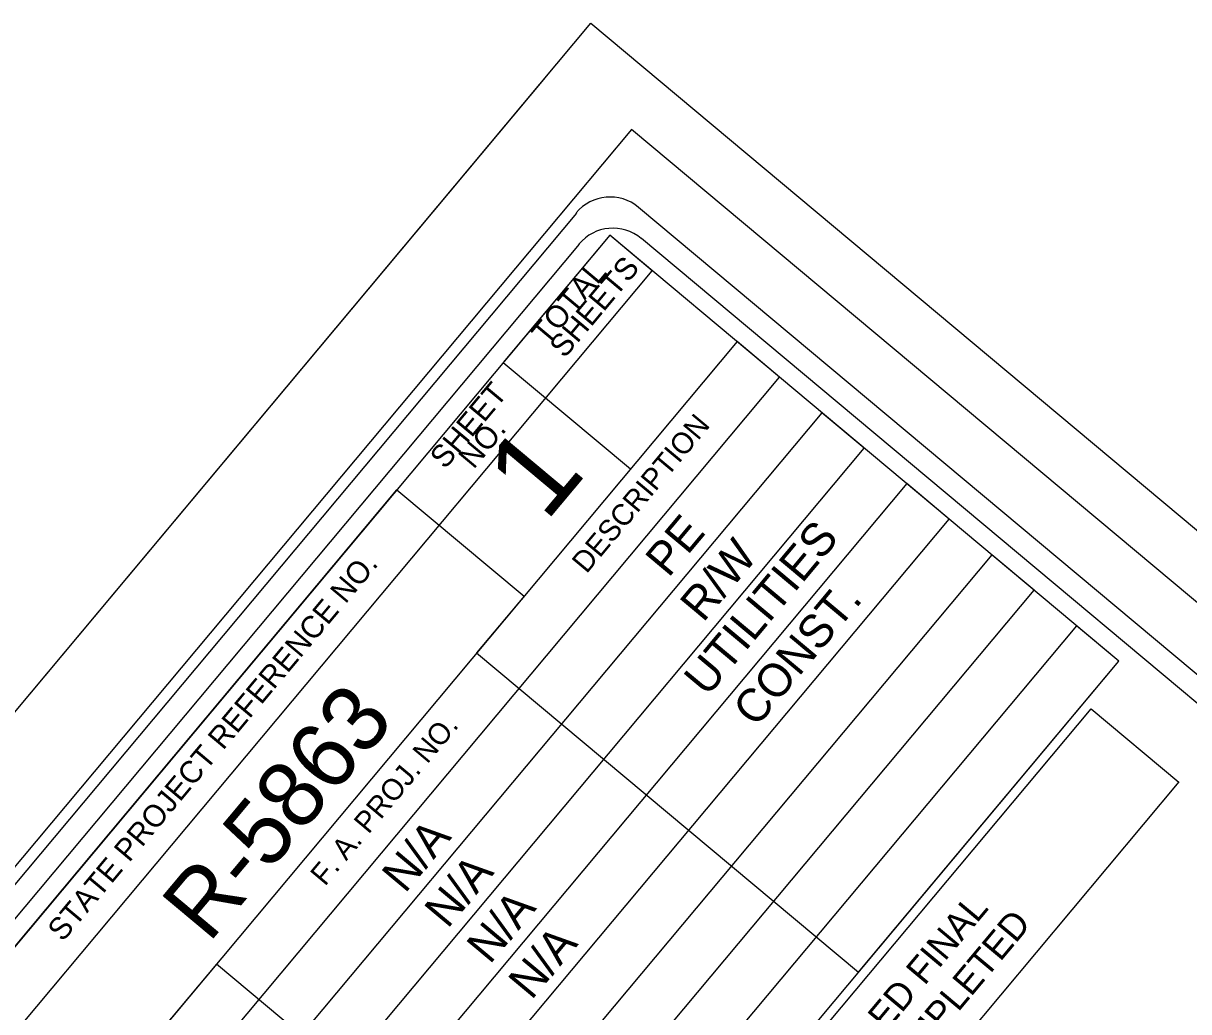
# Model space of a CAD drawing. Extents: x 555292 to 2368606, y 503623 to 1171444.
# Drawn here: x 2359845 to 2361161, y 1167910 to 1169027 of the extents above; entities that cross this region are included whole.
import ezdxf

# ---------------------------------------------------------------- set-up
doc = ezdxf.new("R2010")
doc.units = 0
for name, color, linetype in [('Default', 7, 'Continuous'), ('Sheet Cutting Line CELL', 7, 'Continuous'), ('Sheet Data Field CELL', 7, 'Continuous'), ('Sheet Plot Border Inside CELL', 7, 'Continuous'), ('Sheet Plot Border Outside CELL', 7, 'Continuous'), ('Sheet Title CELL', 7, 'Continuous')]:
    doc.layers.add(name, color=color, linetype=linetype)

msp = doc.modelspace()

# ---------------------------------------------------------------- linework, layer by layer
at = {"layer": 'Default'}
for p, q in [((2360346.1, 1167409.3), (2361051.1, 1168252.2)), ((2361051.2, 1168252.1), (2361150.2, 1168169.3)), ((2361150.1, 1168169.4), (2360445.1, 1167326.5))]:
    msp.add_line(p, q, dxfattribs=at)
at = {"layer": 'Sheet Cutting Line CELL'}
msp.add_line((2355032.5, 1162506.7), (2360434.7, 1168965.2), dxfattribs=at)
at = {"layer": 'Sheet Plot Border Inside CELL'}
msp.add_lwpolyline([(2359232.5, 1159130.5), (2364578.6, 1165521.9), (2360532, 1168906.6), (2355185.9, 1162515.2)], close=True, dxfattribs=at)
at = {"layer": 'Sheet Plot Border Outside CELL'}
for p, q in [((2355032.5, 1162506.7), (2360486, 1169026.6)), ((2360486, 1169026.6), (2364704.7, 1165497.9))]:
    msp.add_line(p, q, dxfattribs=at)
at = {"layer": 'Sheet Title CELL'}
for points in [[(2364490.3, 1165514.3), (2360540, 1168818.4)], [(2360469.6, 1168812.2), (2355721.7, 1163136)], [(2359673, 1167692.4), (2360555.2, 1168747.1), (2360507.3, 1168787.2), (2359625.1, 1167732.4), (2360200.4, 1167251.3), (2360494.4, 1167602.8), (2360063, 1167963.6), (2359889.3, 1167756), (2359745.4, 1167876.3), (2360266.8, 1168499.5), (2360410.5, 1168379.2), (2360356.9, 1168315.2), (2360788.4, 1167954.3), (2361082.6, 1168306), (2360507.3, 1168787.2), (2360387, 1168643.4), (2360530.8, 1168523.1)], [(2360472.7, 1168777), (2355917.5, 1163331)], [(2360472.7, 1168777), (2355917.5, 1163331)], [(2363745.6, 1166104.6), (2360543.1, 1168783.3)], [(2360200.4, 1167251.3), (2361082.6, 1168306), (2361034.7, 1168346), (2360152.4, 1167291.4), (2360104.5, 1167331.5), (2360986.7, 1168386.1), (2360938.8, 1168426.2), (2360056.6, 1167371.6), (2360008.6, 1167411.7), (2360890.8, 1168466.4), (2360842.9, 1168506.5), (2359960.7, 1167451.8), (2359912.8, 1167491.8), (2360794.9, 1168546.6), (2360747, 1168586.6), (2359864.8, 1167531.9), (2359816.9, 1167572), (2360699.1, 1168626.7), (2360651.1, 1168666.9), (2359768.9, 1167612.2)]]:
    msp.add_lwpolyline(points, dxfattribs=at)
for centre in [(2360507.7, 1168780.3), (2360510.9, 1168745.1)]:
    msp.add_arc(centre, 50, 50.0895, 140.0895, dxfattribs=at)

# ---------------------------------------------------------------- texts
at = {"layer": 'Default'}
for s, p in [('DOCUMENT NOT CONSIDERED FINAL', (2360464, 1167461.6)), ('UNLESS ALL SIGNATURES COMPLETED', (2360483.2, 1167409.3))]:
    msp.add_text(s, height=30.213, rotation=50.0895, dxfattribs=at).set_placement(p)
at = {"layer": 'Sheet Data Field CELL'}
for s, height, p in [('PE', 37.5, (2360573.7, 1168399.3)), ('UTILITIES', 37.5, (2360617.3, 1168264.7)), ('R/W', 37.5, (2360612.9, 1168348.7)), ('CONST.', 37.5, (2360672.6, 1168229.9)), ('R-5863', 75, (2360054.4, 1167986.2)), ('N/A', 37.5, (2360276, 1168042.6)), ('N/A', 37.5, (2360324.1, 1168002.7)), ('N/A', 37.5, (2360371.8, 1167962.4)), ('N/A', 37.5, (2360418.9, 1167922.1))]:
    msp.add_text(s, height=height, rotation=50.0895, dxfattribs=at).set_placement(p)
at = {"layer": 'Sheet Title CELL'}
for s, height, p in [('SHEETS', 25, (2360456.3, 1168647.2)), ('TOTAL', 25, (2360436.1, 1168661.9)), ('SHEET', 25, (2360321.3, 1168521.9)), ('DESCRIPTION', 24, (2360481.1, 1168403.9)), ('NO.', 25, (2360353.6, 1168522)), ('1', 96.8, (2360435.1, 1168462)), ('STATE PROJECT REFERENCE NO.', 24.999, (2359889.4, 1167987.9)), ('F. A. PROJ. NO.', 24, (2360185.6, 1168050.8))]:
    msp.add_text(s, height=height, rotation=50.0895, dxfattribs=at).set_placement(p)

doc.saveas('drawing.dxf')
